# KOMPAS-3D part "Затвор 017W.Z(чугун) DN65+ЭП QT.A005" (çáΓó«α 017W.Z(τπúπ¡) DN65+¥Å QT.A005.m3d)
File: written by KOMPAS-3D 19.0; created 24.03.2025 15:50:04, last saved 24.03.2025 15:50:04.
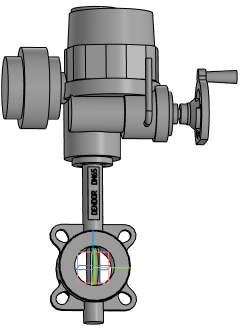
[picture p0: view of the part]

Document properties: Полное имя файла: Затвор 017W.Z(чугун) DN65+ЭП QT.A005.a3d

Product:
- Part/product: Затвор 017W.Z(чугун) DN65+ЭП QT.A005
    Масса: 40.1759

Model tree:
1. Операция без истории:1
